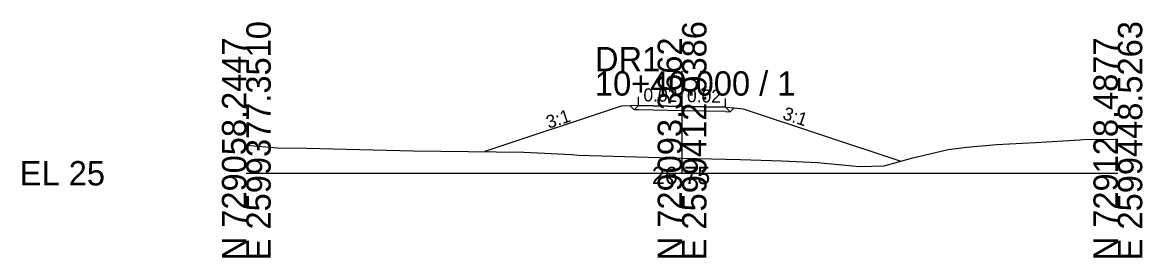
# Model space of a CAD drawing. Extents: x -26 to 1162, y -10 to 9515.
# Drawn here: x -25.7 to 102.8, y 1990.3 to 2017.3 of the extents above; entities that cross this region are included whole.
import ezdxf

# ---------------------------------------------------------------- set-up
doc = ezdxf.new("R2010")
doc.units = 0
for name, color, linetype in [('Exist Cross Section Cell', 7, 'Continuous'), ('Exist XS Center Line Elevation Label', 7, 'Continuous'), ('Exist XS Ground Line', 7, 'Continuous'), ('Prop XS Ditch Slope Text', 7, 'Continuous'), ('Prop XS Dump Level', 7, 'Continuous'), ('Prop XS EOT Tick Mark', 7, 'Continuous'), ('Prop XS Finish Grade', 7, 'Continuous'), ('Prop XS Finish Grade Earthwork', 7, 'Continuous'), ('Prop XS Finish Grade Pavement', 7, 'Continuous'), ('Prop XS Pvmt Edge Slope', 7, 'Continuous'), ('Prop XS SE Text', 7, 'Continuous'), ('Prop XS Subgrade Earthwork', 7, 'Continuous')]:
    doc.layers.add(name, color=color, linetype=linetype)

msp = doc.modelspace()

# ---------------------------------------------------------------- linework, layer by layer
at = {"layer": 'Exist Cross Section Cell'}
for p, q in [((50, 2000), (50, 2011.72)), ((0, 2000), (50, 2000)), ((50, 2000), (100, 2000))]:
    msp.add_line(p, q, dxfattribs=at)
at = {"layer": 'Exist XS Ground Line'}
msp.add_lwpolyline([(0, 2003.21), (3.57, 2002.92), (6.89, 2002.9), (19.15, 2002.59), (31.86, 2002.44), (37.34, 2002.14), (38.09, 2002.09), (46.11, 2001.84), (50, 2001.75), (56.69, 2001.6), (61.44, 2001.44), (65.53, 2001.25), (70.35, 2000.76), (73.18, 2000.87), (76.47, 2001.76), (80.52, 2002.75), (82.69, 2002.99), (86.06, 2003.32), (90.54, 2003.53), (95.63, 2003.84), (96.51, 2003.91), (100, 2003.87)], dxfattribs=at)
at = {"layer": 'Prop XS Dump Level'}
for p, q in [((50, 2007.68), (45, 2007.78)), ((45, 2007.78), (50, 2007.68)), ((55, 2007.58), (50, 2007.68)), ((50, 2007.68), (55, 2007.58))]:
    msp.add_line(p, q, dxfattribs=at)
at = {"layer": 'Prop XS EOT Tick Mark'}
for p, q in [((45, 2007.78), (45, 2008.78)), ((55, 2007.58), (55, 2008.58))]:
    msp.add_line(p, q, dxfattribs=at)
at = {"layer": 'Prop XS Finish Grade'}
for p, q in [((45, 2007.78), (44.06, 2007.74)), ((55, 2007.58), (55.98, 2007.5))]:
    msp.add_line(p, q, dxfattribs=at)
at = {"layer": 'Prop XS Finish Grade Earthwork'}
for p, q in [((43, 2007.7), (27.38, 2002.49)), ((44.06, 2007.74), (43, 2007.7)), ((55.98, 2007.5), (57, 2007.42)), ((57, 2007.42), (75.11, 2001.39))]:
    msp.add_line(p, q, dxfattribs=at)
at = {"layer": 'Prop XS Finish Grade Pavement'}
for p, q in [((45, 2007.78), (50, 2007.68)), ((50, 2007.68), (55, 2007.58))]:
    msp.add_line(p, q, dxfattribs=at)
at = {"layer": 'Prop XS Pvmt Edge Slope'}
for p, q in [((44.06, 2007.74), (44.51, 2007.29)), ((45, 2007.78), (44.51, 2007.29)), ((55, 2007.58), (55.51, 2007.07)), ((55.98, 2007.5), (55.51, 2007.07))]:
    msp.add_line(p, q, dxfattribs=at)
at = {"layer": 'Prop XS Subgrade Earthwork'}
for p, q in [((44.51, 2007.29), (44.06, 2007.74)), ((45, 2007.28), (44.51, 2007.29)), ((50, 2007.18), (45, 2007.28)), ((55, 2007.08), (50, 2007.18)), ((55, 2007.08), (55.51, 2007.07)), ((55.51, 2007.07), (55.98, 2007.5)), ((55.51, 2007.07), (55.98, 2007.5))]:
    msp.add_line(p, q, dxfattribs=at)

# ---------------------------------------------------------------- texts
at = {"layer": 'Exist Cross Section Cell'}
for s, p in [('E 2599377.3510', (2.8, 1990)), ('E 2599412.9386', (52.8, 1990)), ('E 2599448.5263', (102.8, 1990)), ('N 729058.2447', (0, 1990)), ('N 729093.3662', (50, 1990)), ('N 729128.4877', (100, 1990))]:
    msp.add_text(s, height=2.8, rotation=90, dxfattribs=at).set_placement(p)
for s, p in [('DR1', (40, 2011.72)), ('10+40.000 / 1', (40, 2008.92)), ('EL 25', (-26, 1998.6))]:
    msp.add_text(s, height=2.8, dxfattribs=at).set_placement(p)
at = {"layer": 'Exist XS Center Line Elevation Label'}
msp.add_text('26.75', height=2, dxfattribs=at).set_placement((46.53, 1998.75))
at = {"layer": 'Prop XS Ditch Slope Text'}
for rotation, p in [(18.4349, (34.69, 2005.1)), (341.5883, (61.43, 2006.26))]:
    msp.add_text('3:1', height=1.5, rotation=rotation, dxfattribs=at).set_placement(p)
at = {"layer": 'Prop XS Dump Level'}
for p in [(43, 2007.66), (57, 2007.38)]:
    msp.add_text('Case1', height=0.04, dxfattribs=at).set_placement(p)
at = {"layer": 'Prop XS SE Text'}
for p in [(45.55, 2008.27), (50.55, 2008.17)]:
    msp.add_text('0.02', height=1.5, rotation=358.8542, dxfattribs=at).set_placement(p)

doc.saveas('drawing.dxf')
